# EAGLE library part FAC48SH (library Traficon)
CONNECTOR female, 48 pins, block, type B, rows ABC, grid 2.54 mm
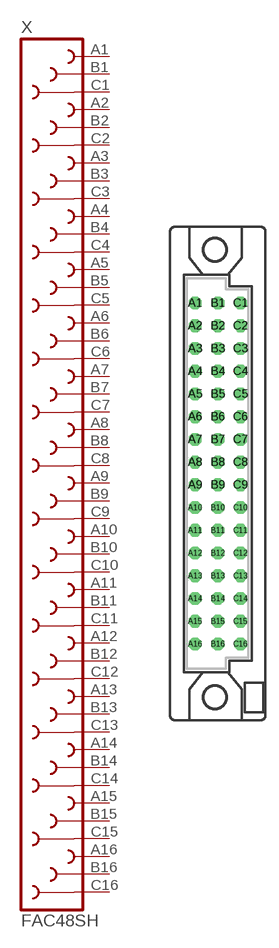
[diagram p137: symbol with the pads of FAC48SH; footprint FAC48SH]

Designator prefix X

## FAC48SH  [FAC48SH]
A1  A1  pas
A2  A2  pas
A3  A3  pas
A4  A4  pas
A5  A5  pas
A6  A6  pas
A7  A7  pas
A8  A8  pas
A9  A9  pas
A10  A10  pas
A11  A11  pas
A12  A12  pas
A13  A13  pas
A14  A14  pas
A15  A15  pas
A16  A16  pas
B1  B1  pas
B2  B2  pas
B3  B3  pas
B4  B4  pas
B5  B5  pas
B6  B6  pas
B7  B7  pas
B8  B8  pas
B9  B9  pas
B10  B10  pas
B11  B11  pas
B12  B12  pas
B13  B13  pas
B14  B14  pas
B15  B15  pas
B16  B16  pas
C1  C1  pas
C2  C2  pas
C3  C3  pas
C4  C4  pas
C5  C5  pas
C6  C6  pas
C7  C7  pas
C8  C8  pas
C9  C9  pas
C10  C10  pas
C11  C11  pas
C12  C12  pas
C13  C13  pas
C14  C14  pas
C15  C15  pas
C16  C16  pas

## Footprint FAC48SH (pad centres in mm)
CONNECTOR female, 48 pins, type B, rows ABC, grid 2.54 mm
drill 0.914 octagon: A1 -2.54,19.05; A2 -2.54,16.51; A3 -2.54,13.97; A4 -2.54,11.43; A5 -2.54,8.89; A6 -2.54,6.35; A7 -2.54,3.81; A8 -2.54,1.27; A9 -2.54,-1.27; A10 -2.54,-3.81; A11 -2.54,-6.35; A12 -2.54,-8.89; A13 -2.54,-11.43; A14 -2.54,-13.97; A15 -2.54,-16.51; A16 -2.54,-19.05; B1 0,19.05; B2 0,16.51; B3 0,13.97; B4 0,11.43; B5 0,8.89; B6 0,6.35; B7 0,3.81; B8 0,1.27; B9 0,-1.27; B10 0,-3.81; B11 0,-6.35; B12 0,-8.89; B13 0,-11.43; B14 0,-13.97; B15 0,-16.51; B16 0,-19.05; C1 2.54,19.05; C2 2.54,16.51; C3 2.54,13.97; C4 2.54,11.43; C5 2.54,8.89; C6 2.54,6.35; C7 2.54,3.81; C8 2.54,1.27; C9 2.54,-1.27; C10 2.54,-3.81; C11 2.54,-6.35; C12 2.54,-8.89; C13 2.54,-11.43; C14 2.54,-13.97; C15 2.54,-16.51; C16 2.54,-19.05
hole 2.794 at -0.305,24.994
hole 2.794 at -0.305,-24.994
